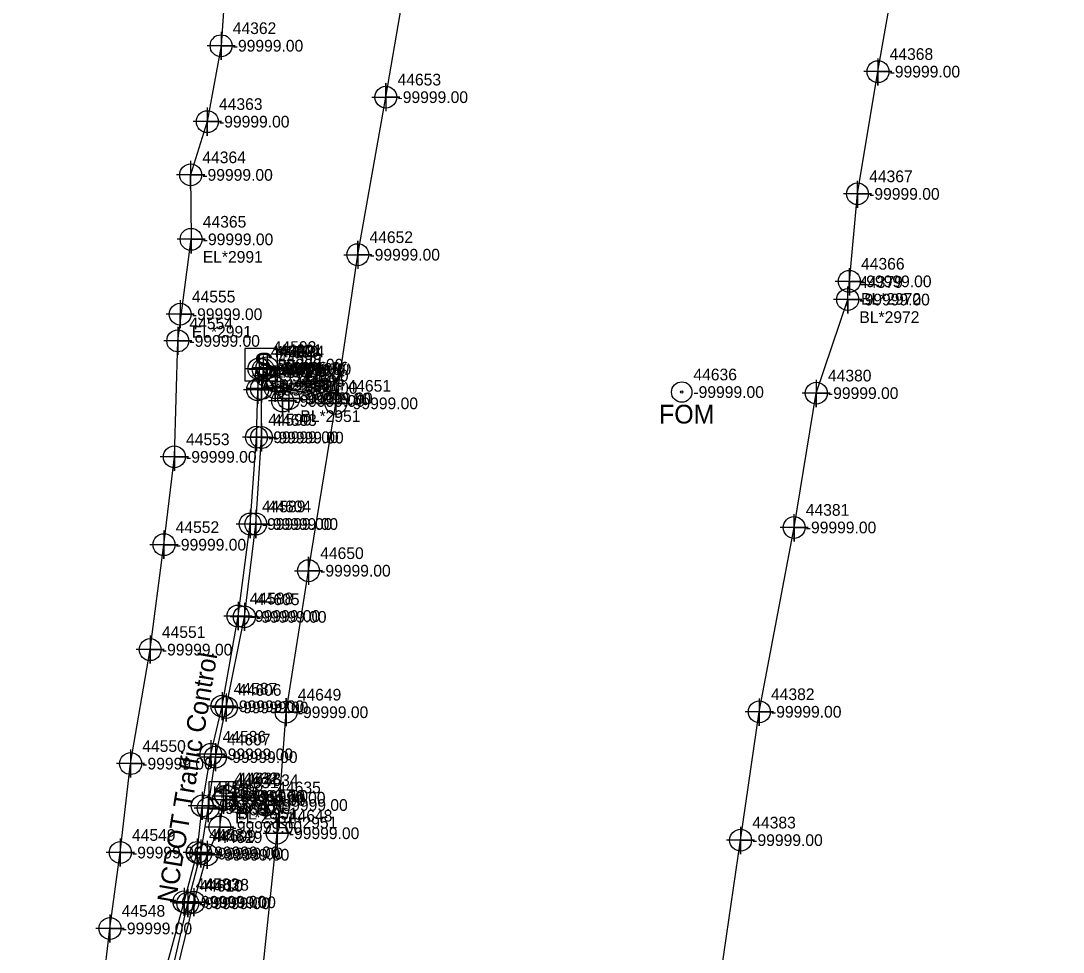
# Model space of a CAD drawing. Extents: x 2083698 to 2094313, y 743246 to 752873.
# Drawn here: x 2086764.9 to 2086987.6, y 747400.8 to 747599.8 of the extents above; entities that cross this region are included whole.
import ezdxf

# ---------------------------------------------------------------- set-up
doc = ezdxf.new("R2010")
doc.units = 0
for name, color, linetype in [('BOUNDARY LINES', 7, 'Continuous'), ('COGO Default Chain', 7, 'Continuous'), ('COGO Default Curve', 7, 'Continuous'), ('COGO Default Parcel', 7, 'Continuous'), ('COGO Default Point Number', 7, 'Continuous'), ('COGO Default Spiral', 7, 'Continuous'), ('CTL North Arrow CELL', 7, 'Continuous'), ('DEEDS_UNROTATED', 7, 'Continuous'), ('Exist Other Culture Fence Line', 7, 'Continuous'), ('Exist Property Iron Pin Leader', 7, 'Continuous'), ('Exist Property Iron Pin Text', 7, 'Continuous'), ('Exist Property Line', 7, 'Continuous'), ('Exist Property Monument Leader', 7, 'Continuous'), ('Exist Property Monument Text', 7, 'Continuous'), ('Exist Right of Way Line', 7, 'Continuous'), ('Exist Right of Way Line Leader', 7, 'Continuous'), ('Exist Right of Way Line Text', 7, 'Continuous'), ('Exist Right of Way Width CELL', 7, 'Continuous'), ('Exist Utilities Gas UG Line SUE LOS B', 7, 'Continuous'), ('Exist Utilities Other Located Object CELL', 7, 'Continuous'), ('Exist Utilities Other Located Object Text', 7, 'Continuous'), ('Exist Utilities Power Joint Use Telephone Cogo Elevation', 7, 'Continuous'), ('Exist Utilities Power Joint Use Telephone Cogo Number', 7, 'Continuous'), ('Exist Utilities Power UG Cable SUE LOS B', 7, 'Continuous'), ('Exist Utilities Power UG Cable SUE LOS B Text', 7, 'Continuous'), ('Exist Utilities Telephone UG Conduit SUE LOS B', 7, 'Continuous'), ('Exist Utilities Water UG Line SUE LOS B', 7, 'Continuous'), ('Old_Level_20', 7, 'Continuous'), ('Scratch_Level_0', 7, 'Continuous'), ('Scratch_Level_2', 7, 'Continuous'), ('Scratch_Level_3', 7, 'Continuous'), ('Scratch_Level_5', 7, 'Continuous')]:
    doc.layers.add(name, color=color, linetype=linetype)

msp = doc.modelspace()

# ---------------------------------------------------------------- linework, layer by layer
at = {"layer": 'COGO Default Curve'}
for points in [[(2086839.88, 747583.52), (2086845.88, 747583.52), (2086842.88, 747583.52), (2086842.88, 747586.52), (2086842.88, 747580.52)], [(2086833.88, 747549.85), (2086839.88, 747549.85), (2086836.88, 747549.85), (2086836.88, 747552.85), (2086836.88, 747546.85)], [(2086829.19, 747518.08), (2086835.19, 747518.08), (2086832.19, 747518.08), (2086832.19, 747521.08), (2086832.19, 747515.08)], [(2086823.35, 747482.32), (2086829.35, 747482.32), (2086826.35, 747482.32), (2086826.35, 747485.32), (2086826.35, 747479.32)], [(2086818.56, 747452.08), (2086824.56, 747452.08), (2086821.56, 747452.08), (2086821.56, 747455.08), (2086821.56, 747449.08)], [(2086816.65, 747426.22), (2086822.65, 747426.22), (2086819.65, 747426.22), (2086819.65, 747429.22), (2086819.65, 747423.22)]]:
    msp.add_lwpolyline(points, dxfattribs=at)
for centre in [(2086842.88, 747583.52), (2086836.88, 747549.85), (2086832.19, 747518.08), (2086826.35, 747482.32), (2086821.56, 747452.08), (2086819.65, 747426.22)]:
    msp.add_circle(centre, 2.34, dxfattribs=at)
at = {"layer": 'COGO Default Point Number'}
for points in [[(2086807.67, 747597.51), (2086807.67, 747591.51), (2086807.67, 747594.51), (2086810.67, 747594.51), (2086804.67, 747594.51)], [(2086804.73, 747581.29), (2086804.73, 747575.29), (2086804.73, 747578.29), (2086807.73, 747578.29), (2086801.73, 747578.29)], [(2086801.17, 747569.91), (2086801.17, 747563.91), (2086801.17, 747566.91), (2086804.17, 747566.91), (2086798.17, 747566.91)], [(2086801.26, 747556.14), (2086801.26, 747550.14), (2086801.26, 747553.14), (2086804.26, 747553.14), (2086798.26, 747553.14)], [(2086798.93, 747540.14), (2086798.93, 747534.14), (2086798.93, 747537.14), (2086801.93, 747537.14), (2086795.93, 747537.14)], [(2086798.41, 747534.43), (2086798.41, 747528.43), (2086798.41, 747531.43), (2086801.41, 747531.43), (2086795.41, 747531.43)], [(2086797.69, 747509.65), (2086797.69, 747503.65), (2086797.69, 747506.65), (2086800.69, 747506.65), (2086794.69, 747506.65)], [(2086795.47, 747490.88), (2086795.47, 747484.88), (2086795.47, 747487.88), (2086798.47, 747487.88), (2086792.47, 747487.88)], [(2086792.52, 747468.46), (2086792.52, 747462.46), (2086792.52, 747465.46), (2086795.52, 747465.46), (2086789.52, 747465.46)], [(2086788.34, 747444.1), (2086788.34, 747438.1), (2086788.34, 747441.1), (2086791.34, 747441.1), (2086785.34, 747441.1)], [(2086786.14, 747425.09), (2086786.14, 747419.09), (2086786.14, 747422.09), (2086789.14, 747422.09), (2086783.14, 747422.09)], [(2086783.93, 747408.87), (2086783.93, 747402.87), (2086783.93, 747405.87), (2086786.93, 747405.87), (2086780.93, 747405.87)]]:
    msp.add_lwpolyline(points, dxfattribs=at)
for centre in [(2086807.67, 747594.51), (2086804.73, 747578.29), (2086801.17, 747566.91), (2086801.26, 747553.14), (2086798.93, 747537.14), (2086798.41, 747531.43), (2086797.69, 747506.65), (2086795.47, 747487.88), (2086792.52, 747465.46), (2086788.34, 747441.1), (2086786.14, 747422.09), (2086783.93, 747405.87)]:
    msp.add_circle(centre, 2.34, dxfattribs=at)
at = {"layer": 'COGO Default Spiral'}
msp.add_line((2086808.03, 747434.19), (2086808.03, 747434.19), dxfattribs=at)
msp.add_lwpolyline([(2086805.08, 747431.46), (2086810.83, 747431.46), (2086810.83, 747437.21), (2086805.08, 747437.21), (2086805.08, 747431.46)], dxfattribs=at)
at = {"layer": 'DEEDS_UNROTATED'}
msp.add_line((2086816.23, 747526.37), (2086816.23, 747526.37), dxfattribs=at)
msp.add_lwpolyline([(2086812.75, 747522.89), (2086819.7, 747522.89), (2086819.7, 747529.84), (2086812.75, 747529.84), (2086812.75, 747522.89)], dxfattribs=at)
at = {"layer": 'Exist Property Iron Pin Text'}
for points in [[(2086815.78, 747528.45), (2086815.78, 747522.45), (2086815.78, 747525.45), (2086818.78, 747525.45), (2086812.78, 747525.45)], [(2086816.67, 747528.34), (2086816.67, 747522.34), (2086816.67, 747525.34), (2086819.67, 747525.34), (2086813.67, 747525.34)], [(2086817.49, 747528.7), (2086817.49, 747522.7), (2086817.49, 747525.7), (2086820.49, 747525.7), (2086814.49, 747525.7)], [(2086817.35, 747527), (2086817.35, 747521), (2086817.35, 747524), (2086820.35, 747524), (2086814.35, 747524)], [(2086815.49, 747524.01), (2086815.49, 747518.01), (2086815.49, 747521.01), (2086818.49, 747521.01), (2086812.49, 747521.01)], [(2086816.29, 747524.24), (2086816.29, 747518.24), (2086816.29, 747521.24), (2086819.29, 747521.24), (2086813.29, 747521.24)], [(2086819.26, 747524.39), (2086819.26, 747518.39), (2086819.26, 747521.39), (2086822.26, 747521.39), (2086816.26, 747521.39)], [(2086820.82, 747521.6), (2086820.82, 747515.6), (2086820.82, 747518.6), (2086823.82, 747518.6), (2086817.82, 747518.6)], [(2086822.12, 747522.1), (2086822.12, 747516.1), (2086822.12, 747519.1), (2086825.12, 747519.1), (2086819.12, 747519.1)], [(2086815.23, 747513.85), (2086815.23, 747507.85), (2086815.23, 747510.85), (2086818.23, 747510.85), (2086812.23, 747510.85)], [(2086816.31, 747513.77), (2086816.31, 747507.77), (2086816.31, 747510.77), (2086819.31, 747510.77), (2086813.31, 747510.77)], [(2086813.9, 747495.3), (2086813.9, 747489.3), (2086813.9, 747492.3), (2086816.9, 747492.3), (2086810.9, 747492.3)], [(2086815.11, 747495.3), (2086815.11, 747489.3), (2086815.11, 747492.3), (2086818.11, 747492.3), (2086812.11, 747492.3)], [(2086811.29, 747475.64), (2086811.29, 747469.64), (2086811.29, 747472.64), (2086814.29, 747472.64), (2086808.29, 747472.64)], [(2086812.64, 747475.46), (2086812.64, 747469.46), (2086812.64, 747472.46), (2086815.64, 747472.46), (2086809.64, 747472.46)], [(2086807.87, 747456.36), (2086807.87, 747450.36), (2086807.87, 747453.36), (2086810.87, 747453.36), (2086804.87, 747453.36)], [(2086808.78, 747456.09), (2086808.78, 747450.09), (2086808.78, 747453.09), (2086811.78, 747453.09), (2086805.78, 747453.09)], [(2086805.49, 747446.09), (2086805.49, 747440.09), (2086805.49, 747443.09), (2086808.49, 747443.09), (2086802.49, 747443.09)], [(2086806.45, 747445.48), (2086806.45, 747439.48), (2086806.45, 747442.48), (2086809.45, 747442.48), (2086803.45, 747442.48)], [(2086808.18, 747436.35), (2086808.18, 747430.35), (2086808.18, 747433.35), (2086811.18, 747433.35), (2086805.18, 747433.35)], [(2086808.69, 747437.16), (2086808.69, 747431.16), (2086808.69, 747434.16), (2086811.69, 747434.16), (2086805.69, 747434.16)], [(2086812.43, 747436.8), (2086812.43, 747430.8), (2086812.43, 747433.8), (2086815.43, 747433.8), (2086809.43, 747433.8)], [(2086803.64, 747435.08), (2086803.64, 747429.08), (2086803.64, 747432.08), (2086806.64, 747432.08), (2086800.64, 747432.08)], [(2086804.93, 747434.59), (2086804.93, 747428.59), (2086804.93, 747431.59), (2086807.93, 747431.59), (2086801.93, 747431.59)], [(2086817.18, 747435.25), (2086817.18, 747429.25), (2086817.18, 747432.25), (2086820.18, 747432.25), (2086814.18, 747432.25)], [(2086807.42, 747430.54), (2086807.42, 747424.54), (2086807.42, 747427.54), (2086810.42, 747427.54), (2086804.42, 747427.54)], [(2086802.57, 747425.12), (2086802.57, 747419.12), (2086802.57, 747422.12), (2086805.57, 747422.12), (2086799.57, 747422.12)], [(2086803.34, 747424.87), (2086803.34, 747418.87), (2086803.34, 747421.87), (2086806.34, 747421.87), (2086800.34, 747421.87)], [(2086804.69, 747424.62), (2086804.69, 747418.62), (2086804.69, 747421.62), (2086807.69, 747421.62), (2086801.69, 747421.62)], [(2086799.76, 747414.57), (2086799.76, 747408.57), (2086799.76, 747411.57), (2086802.76, 747411.57), (2086796.76, 747411.57)], [(2086800.55, 747414.25), (2086800.55, 747408.25), (2086800.55, 747411.25), (2086803.55, 747411.25), (2086797.55, 747411.25)], [(2086801.82, 747414.46), (2086801.82, 747408.46), (2086801.82, 747411.46), (2086804.82, 747411.46), (2086798.82, 747411.46)]]:
    msp.add_lwpolyline(points, dxfattribs=at)
for centre in [(2086815.78, 747525.45), (2086816.67, 747525.34), (2086817.49, 747525.7), (2086817.35, 747524), (2086815.49, 747521.01), (2086816.29, 747521.24), (2086819.26, 747521.39), (2086820.82, 747518.6), (2086822.12, 747519.1), (2086815.23, 747510.85), (2086816.31, 747510.77), (2086813.9, 747492.3), (2086815.11, 747492.3), (2086811.29, 747472.64), (2086812.64, 747472.46), (2086807.87, 747453.36), (2086808.78, 747453.09), (2086805.49, 747443.09), (2086806.45, 747442.48), (2086808.69, 747434.16), (2086812.43, 747433.8), (2086803.64, 747432.08), (2086804.93, 747431.59), (2086808.18, 747433.35), (2086817.18, 747432.25), (2086807.42, 747427.54), (2086802.57, 747422.12), (2086803.34, 747421.87), (2086804.69, 747421.62), (2086799.76, 747411.57), (2086801.82, 747411.46), (2086800.55, 747411.25)]:
    msp.add_circle(centre, 2.34, dxfattribs=at)
at = {"layer": 'Exist Right of Way Line Text'}
for points in [[(2086948, 747591.8), (2086948.03, 747585.98), (2086948.01, 747588.98), (2086951.03, 747588.98), (2086945.03, 747588.98)], [(2086943.62, 747565.67), (2086943.65, 747559.85), (2086943.64, 747562.85), (2086946.65, 747562.85), (2086940.65, 747562.85)], [(2086941.89, 747546.97), (2086941.92, 747541.16), (2086941.9, 747544.16), (2086944.92, 747544.16), (2086938.92, 747544.16)], [(2086941.53, 747543.09), (2086941.56, 747537.27), (2086941.54, 747540.27), (2086944.56, 747540.27), (2086938.56, 747540.27)], [(2086934.82, 747523.08), (2086934.85, 747517.27), (2086934.83, 747520.27), (2086937.85, 747520.27), (2086931.85, 747520.27)], [(2086930.08, 747494.37), (2086930.11, 747488.56), (2086930.1, 747491.56), (2086933.11, 747491.56), (2086927.11, 747491.56)], [(2086922.65, 747454.98), (2086922.68, 747449.17), (2086922.66, 747452.17), (2086925.68, 747452.17), (2086919.68, 747452.17)], [(2086918.64, 747427.56), (2086918.68, 747421.74), (2086918.66, 747424.74), (2086921.68, 747424.74), (2086915.68, 747424.74)]]:
    msp.add_lwpolyline(points, dxfattribs=at)
for centre in [(2086948.03, 747588.98), (2086943.65, 747562.85), (2086941.92, 747544.16), (2086941.56, 747540.27), (2086934.85, 747520.27), (2086930.11, 747491.56), (2086922.68, 747452.17), (2086918.68, 747424.74)]:
    msp.add_circle(centre, 2.34, dxfattribs=at)
at = {"layer": 'Exist Utilities Gas UG Line SUE LOS B'}
msp.add_lwpolyline([(2086796.8, 747117.35), (2086798.65, 747140.38), (2086801.61, 747173.33), (2086800.71, 747180.23), (2086792.58, 747192.4), (2086794.18, 747206.52), (2086796.05, 747225.41), (2086797.06, 747240.82), (2086798.48, 747264.57), (2086809.12, 747340.59), (2086814.47, 747376.66), (2086819.65, 747426.22), (2086821.56, 747452.08), (2086826.35, 747482.32), (2086832.19, 747518.08), (2086836.88, 747549.85), (2086842.88, 747583.52), (2086846.67, 747605.55)], dxfattribs=at)
at = {"layer": 'Exist Utilities Other Located Object CELL'}
for radius in [2.18, 0.24]:
    msp.add_circle((2086906.1, 747520.5), radius, dxfattribs=at)
at = {"layer": 'Exist Utilities Power UG Cable SUE LOS B'}
for points in [[(2086784.82, 747349.43), (2086783.36, 747352.89), (2086785.78, 747363.55), (2086789.79, 747377.88), (2086792.21, 747384.98), (2086794.94, 747393.7), (2086799.76, 747411.57), (2086802.57, 747422.12), (2086803.64, 747432.08), (2086805.49, 747443.09), (2086807.87, 747453.36), (2086811.29, 747472.64), (2086813.9, 747492.3), (2086815.23, 747510.85), (2086815.49, 747521.01), (2086815.78, 747525.45)], [(2086792.4, 747362.83), (2086793.52, 747369.81), (2086794.39, 747372.48), (2086794.21, 747376.72), (2086796.46, 747393.26), (2086800.55, 747411.25), (2086803.34, 747421.87), (2086804.93, 747431.59), (2086806.45, 747442.48), (2086808.78, 747453.09), (2086812.64, 747472.46), (2086815.11, 747492.3), (2086816.31, 747510.77), (2086816.29, 747521.24), (2086817.49, 747525.7)], [(2086822.12, 747519.1), (2086820.82, 747518.6), (2086819.26, 747521.39), (2086817.35, 747524), (2086816.67, 747525.34)], [(2086808.69, 747434.16), (2086812.43, 747433.8), (2086817.18, 747432.25)], [(2086794.82, 747372.46), (2086795.34, 747376.99), (2086797.28, 747392.89), (2086801.82, 747411.46), (2086804.69, 747421.62), (2086807.42, 747427.54), (2086808.18, 747433.35)]]:
    msp.add_lwpolyline(points, dxfattribs=at)
at = {"layer": 'Exist Utilities Telephone UG Conduit SUE LOS B'}
for points in [[(2086941.92, 747544.16), (2086943.65, 747562.85), (2086948.03, 747588.98), (2086955.82, 747633.28), (2086958.95, 747657.59), (2086966.71, 747687.3), (2086975.87, 747729.17), (2086978.35, 747743.27), (2086979.7, 747756.74), (2086987.6, 747783.9)], [(2086868.07, 747136.76), (2086871.7, 747147.8), (2086874.69, 747167.4), (2086879.29, 747187.33), (2086884.94, 747228.71), (2086891.19, 747256.94), (2086892.05, 747265.63), (2086899.19, 747309.15), (2086902.09, 747328.05), (2086909.27, 747364.33), (2086913.7, 747390.55), (2086918.68, 747424.74), (2086922.68, 747452.17), (2086930.11, 747491.56), (2086934.85, 747520.27), (2086941.56, 747540.27)]]:
    msp.add_lwpolyline(points, dxfattribs=at)
at = {"layer": 'Exist Utilities Water UG Line SUE LOS B'}
for points in [[(2086808.39, 747605.15), (2086807.67, 747594.51), (2086804.73, 747578.29), (2086801.17, 747566.91), (2086801.26, 747553.14)], [(2086765.76, 747209.31), (2086765.31, 747211.11), (2086764.89, 747212.52), (2086765.89, 747224.94), (2086766.41, 747236.79), (2086766.33, 747245.42), (2086766.7, 747255.56), (2086767.61, 747267.76), (2086768.34, 747283), (2086769.39, 747298.17), (2086771.07, 747310.62), (2086774.35, 747330.83), (2086777.67, 747356.28), (2086780.41, 747375.94), (2086783.93, 747405.87), (2086786.14, 747422.09), (2086788.34, 747441.1), (2086792.52, 747465.46), (2086795.47, 747487.88), (2086797.69, 747506.65), (2086798.41, 747531.43), (2086801.26, 747553.14)]]:
    msp.add_lwpolyline(points, dxfattribs=at)

# ---------------------------------------------------------------- texts
at = {"layer": 'BOUNDARY LINES'}
msp.add_text('-99999.00', height=2.5, dxfattribs=at).set_placement((2086818.73, 747525.12))
at = {"layer": 'COGO Default Chain'}
for p in [(2086845.38, 747582.27), (2086839.38, 747548.6), (2086834.69, 747516.83), (2086828.85, 747481.07), (2086824.06, 747450.83), (2086822.15, 747424.97)]:
    msp.add_text('-99999.00', height=2.5, dxfattribs=at).set_placement(p)
at = {"layer": 'COGO Default Parcel'}
msp.add_text('44636', height=2.5, dxfattribs=at).set_placement((2086908.6, 747523))
at = {"layer": 'COGO Default Spiral'}
for p in [(2086805.87, 747433.71), (2086808.43, 747432.19)]:
    msp.add_text('H', height=2.5, dxfattribs=at).set_placement(p)
at = {"layer": 'CTL North Arrow CELL'}
msp.add_text('44593', height=2.5, dxfattribs=at).set_placement((2086818.73, 747528.87))
at = {"layer": 'DEEDS_UNROTATED'}
msp.add_text('S', height=5, dxfattribs=at).set_placement((2086814.59, 747523.87))
at = {"layer": 'Exist Other Culture Fence Line'}
msp.add_text('-99999.00', height=2.5, dxfattribs=at).set_placement((2086810.53, 747432.94))
at = {"layer": 'Exist Property Iron Pin Leader'}
for s, p in [('44592', (2086818.28, 747527.95)), ('44600', (2086819.17, 747527.84)), ('44601', (2086819.99, 747528.2)), ('44599', (2086819.85, 747526.5)), ('44591', (2086817.99, 747523.51)), ('44602', (2086818.79, 747523.74)), ('44598', (2086821.76, 747523.89)), ('44597', (2086823.32, 747521.1)), ('44596', (2086824.62, 747521.6)), ('44590', (2086817.73, 747513.35)), ('44603', (2086818.81, 747513.27)), ('44589', (2086816.4, 747494.8)), ('44604', (2086817.61, 747494.8)), ('44588', (2086813.79, 747475.14)), ('44605', (2086815.14, 747474.96)), ('44587', (2086810.37, 747455.86)), ('44606', (2086811.28, 747455.59)), ('44586', (2086807.99, 747445.59)), ('44607', (2086808.95, 747444.98)), ('44631', (2086810.68, 747435.85)), ('44633', (2086811.19, 747436.66)), ('44634', (2086814.93, 747436.3)), ('44585', (2086806.14, 747434.58)), ('44608', (2086807.43, 747434.09)), ('44635', (2086819.68, 747434.75)), ('44630', (2086809.92, 747430.04)), ('44584', (2086805.07, 747424.62)), ('44609', (2086805.84, 747424.37)), ('44629', (2086807.19, 747424.12)), ('44583', (2086802.26, 747414.07)), ('44610', (2086803.05, 747413.75)), ('44628', (2086804.32, 747413.96))]:
    msp.add_text(s, height=2.5, dxfattribs=at).set_placement(p)
at = {"layer": 'Exist Property Line'}
for p in [(2086810.17, 747593.26), (2086807.23, 747577.04), (2086803.67, 747565.66), (2086803.76, 747551.89), (2086801.43, 747535.89), (2086800.91, 747530.18), (2086800.19, 747505.4), (2086797.97, 747486.63), (2086795.02, 747464.21), (2086790.84, 747439.85), (2086788.64, 747420.84), (2086786.43, 747404.62)]:
    msp.add_text('-99999.00', height=2.5, dxfattribs=at).set_placement(p)
at = {"layer": 'Exist Property Monument Leader'}
for s, p in [('EL*2951', (2086818.28, 747520.45)), ('BL*2951', (2086819.99, 747520.7)), ('EL*2951', (2086819.17, 747520.34)), ('BL*2951', (2086824.62, 747514.1)), ('BL*2951', (2086811.19, 747429.16)), ('EL*2951', (2086810.68, 747428.35)), ('EL*2951', (2086819.68, 747427.25))]:
    msp.add_text(s, height=2.5, dxfattribs=at).set_placement(p)
at = {"layer": 'Exist Property Monument Text'}
for p in [(2086818.28, 747524.2), (2086819.17, 747524.09), (2086819.85, 747522.75), (2086819.99, 747524.45), (2086817.99, 747519.76), (2086818.79, 747519.99), (2086821.76, 747520.14), (2086823.32, 747517.35), (2086824.62, 747517.85), (2086817.73, 747509.6), (2086818.81, 747509.52), (2086816.4, 747491.05), (2086817.61, 747491.05), (2086813.79, 747471.39), (2086815.14, 747471.21), (2086810.37, 747452.11), (2086811.28, 747451.84), (2086807.99, 747441.84), (2086808.95, 747441.23), (2086810.68, 747432.1), (2086811.19, 747432.91), (2086814.93, 747432.55), (2086806.14, 747430.83), (2086807.43, 747430.34), (2086819.68, 747431), (2086809.92, 747426.29), (2086805.07, 747420.87), (2086805.84, 747420.62), (2086807.19, 747420.37), (2086802.26, 747410.32), (2086803.05, 747410), (2086804.32, 747410.21)]:
    msp.add_text('-99999.00', height=2.5, dxfattribs=at).set_placement(p)
at = {"layer": 'Exist Right of Way Line'}
for s, p in [('44362', (2086810.17, 747597.01)), ('44363', (2086807.23, 747580.79)), ('44364', (2086803.67, 747569.41)), ('44365', (2086803.76, 747555.64)), ('44555', (2086801.43, 747539.64)), ('44554', (2086800.91, 747533.93)), ('44553', (2086800.19, 747509.15)), ('44552', (2086797.97, 747490.38)), ('44551', (2086795.02, 747467.96)), ('44550', (2086790.84, 747443.6)), ('44549', (2086788.64, 747424.59)), ('44548', (2086786.43, 747408.37))]:
    msp.add_text(s, height=2.5, dxfattribs=at).set_placement(p)
at = {"layer": 'Exist Right of Way Line Leader'}
for s, p in [('44368', (2086950.53, 747591.48)), ('44367', (2086946.15, 747565.35)), ('44366', (2086944.42, 747546.66)), ('44379', (2086944.06, 747542.77)), ('44380', (2086937.35, 747522.77)), ('44381', (2086932.61, 747494.06)), ('44382', (2086925.18, 747454.67)), ('44383', (2086921.18, 747427.24))]:
    msp.add_text(s, height=2.5, dxfattribs=at).set_placement(p)
at = {"layer": 'Exist Right of Way Width CELL'}
for p in [(2086803.76, 747548.14), (2086801.43, 747532.14)]:
    msp.add_text('EL*2991', height=2.5, dxfattribs=at).set_placement(p)
at = {"layer": 'Exist Utilities Other Located Object Text'}
msp.add_text('FOM', height=4, dxfattribs=at).set_placement((2086901.23, 747513.78))
at = {"layer": 'Exist Utilities Power Joint Use Telephone Cogo Elevation'}
for p in [(2086820.42, 747524.16), (2086824.99, 747517.9)]:
    msp.add_text('-99999.00', height=2.5, dxfattribs=at).set_placement(p)
at = {"layer": 'Exist Utilities Power Joint Use Telephone Cogo Number'}
for s, p in [('44594', (2086820.42, 747527.91)), ('44595', (2086824.99, 747521.65))]:
    msp.add_text(s, height=2.5, dxfattribs=at).set_placement(p)
at = {"layer": 'Exist Utilities Power UG Cable SUE LOS B Text'}
msp.add_text('NCDOT Traffic Control', height=4, rotation=80.4541, dxfattribs=at).set_placement((2086797.94, 747411.11))
at = {"layer": 'Old_Level_20'}
for s, p in [('44653', (2086845.38, 747586.02)), ('44652', (2086839.38, 747552.35)), ('44651', (2086834.69, 747520.58)), ('44650', (2086828.85, 747484.82)), ('44649', (2086824.06, 747454.58)), ('44648', (2086822.15, 747428.72))]:
    msp.add_text(s, height=2.5, dxfattribs=at).set_placement(p)
at = {"layer": 'Scratch_Level_0'}
msp.add_text('-99999.00', height=2.5, dxfattribs=at).set_placement((2086908.6, 747519.25))
at = {"layer": 'Scratch_Level_2'}
for p in [(2086950.53, 747587.73), (2086946.15, 747561.6), (2086944.42, 747542.91), (2086944.06, 747539.02), (2086937.35, 747519.02), (2086932.61, 747490.31), (2086925.18, 747450.92), (2086921.18, 747423.49)]:
    msp.add_text('-99999.00', height=2.5, dxfattribs=at).set_placement(p)
at = {"layer": 'Scratch_Level_3'}
for p in [(2086944.42, 747539.16), (2086944.06, 747535.27)]:
    msp.add_text('BL*2972', height=2.5, dxfattribs=at).set_placement(p)
at = {"layer": 'Scratch_Level_5'}
msp.add_text('44632', height=2.5, dxfattribs=at).set_placement((2086810.53, 747436.69))

doc.saveas('drawing.dxf')
